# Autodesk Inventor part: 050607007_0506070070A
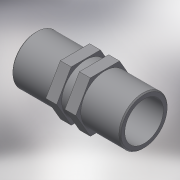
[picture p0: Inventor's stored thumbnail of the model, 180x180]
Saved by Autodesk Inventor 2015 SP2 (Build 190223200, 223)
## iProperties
Created: 2017-05
Part Number: 050607007_0506070070A
Material: Generic
Description: PLASSON NIPPLE 3/4"-3/4"
Document SubType Name: Modeling
Designer: KIM
Density: 1 g/cm^3
Appearance: Default
Author: KIM
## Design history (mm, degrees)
derived "050607.ipt"
feature "Solid1::050607.ipt"
tag "TaggingFeature1"
body "Solid1"
other parameters: "d0" = 49, "d1" = 26.441, "d2" = 27, "d3" = 21.1528, "d4" = 18, "d5" = 18, "d6" = 4.9, "d8" = 0.49, "d12" = 0, "H_" = 49, "R_" = 26.441, "E_" = 27, "l_2" = 18
